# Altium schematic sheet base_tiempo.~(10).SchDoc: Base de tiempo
size A4; Revision: 1
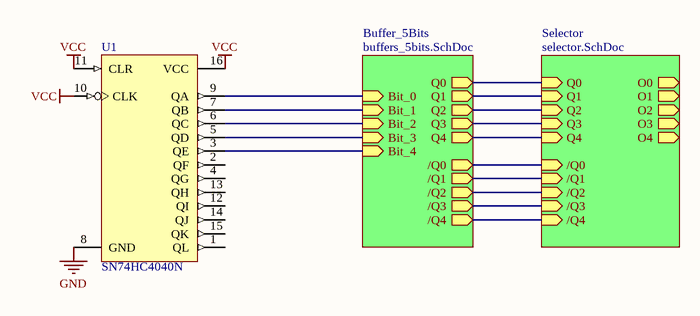
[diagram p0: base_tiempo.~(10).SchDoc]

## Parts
U1  SN74HC4040N  [N016]

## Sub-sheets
Buffer_5Bits = buffers_5bits.SchDoc: Bit_0 (in), Bit_1 (in), Bit_2 (in), Bit_3 (in), Bit_4 (in), Q0 (out), Q1 (out), Q2 (out), Q3 (out), Q4 (out), /Q0 (out), /Q1 (out), /Q2 (out), /Q3 (out), /Q4 (out)
Selector = selector.SchDoc: Q0 (in), Q1 (in), Q2 (in), Q3 (in), Q4 (in), /Q0 (in), /Q1 (in), /Q2 (in), /Q3 (in), /Q4 (in), O0 (out), O1 (out), O2 (out), O3 (out), O4 (out)

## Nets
GND: U1.8(GND)
VCC: U1.10(CLK) U1.11(CLR) U1.16(VCC)
NetU1_3: U1.3(QE) ; sheet Buffer_5Bits/Bit_4
NetU1_5: U1.5(QD) ; sheet Buffer_5Bits/Bit_3
NetU1_6: U1.6(QC) ; sheet Buffer_5Bits/Bit_2
NetU1_7: U1.7(QB) ; sheet Buffer_5Bits/Bit_1
NetU1_9: U1.9(QA) ; sheet Buffer_5Bits/Bit_0
(unnamed): sheet Buffer_5Bits/Q0, sheet Selector/Q0
(unnamed): sheet Buffer_5Bits/Q1, sheet Selector/Q1  [a separate net that carries the same name]
(unnamed): sheet Buffer_5Bits/Q2, sheet Selector/Q2  [a separate net that carries the same name]
(unnamed): sheet Buffer_5Bits/Q3, sheet Selector/Q3  [a separate net that carries the same name]
(unnamed): sheet Buffer_5Bits/Q4, sheet Selector/Q4  [a separate net that carries the same name]
(unnamed): sheet Buffer_5Bits//Q0, sheet Selector//Q0  [a separate net that carries the same name]
(unnamed): sheet Buffer_5Bits//Q1, sheet Selector//Q1  [a separate net that carries the same name]
(unnamed): sheet Buffer_5Bits//Q2, sheet Selector//Q2  [a separate net that carries the same name]
(unnamed): sheet Buffer_5Bits//Q3, sheet Selector//Q3  [a separate net that carries the same name]
(unnamed): sheet Buffer_5Bits//Q4, sheet Selector//Q4  [a separate net that carries the same name]

Not connected (* = marked no-connect by the designer): U1 1(QL) 2(QF) 4(QG) 12(QI) 13(QH) 14(QJ) 15(QK)

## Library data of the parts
U1 = SN74HC4040N: 12-Bit Asynchronous Binary Counter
